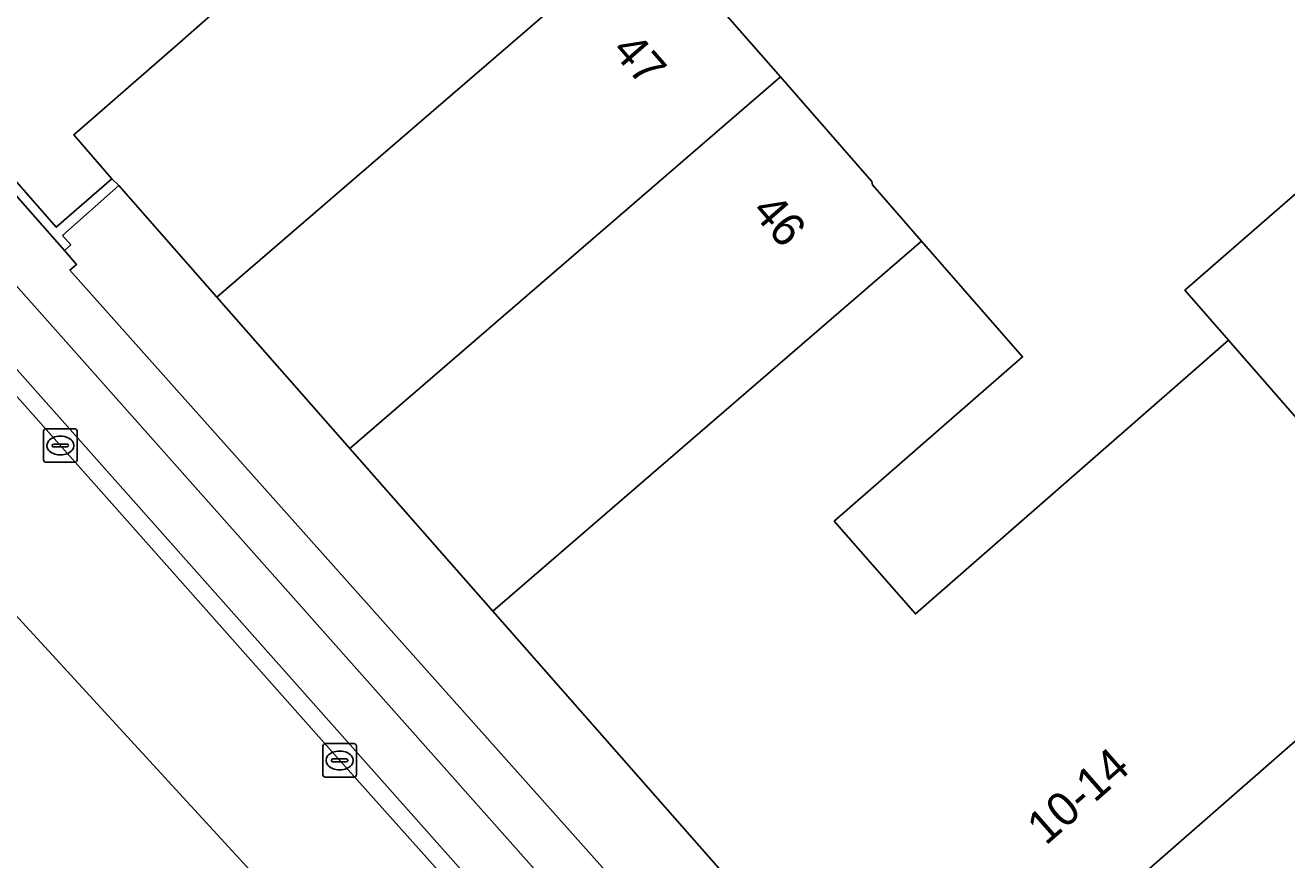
# Model space of a CAD drawing. Extents: x 160663 to 161506, y 382245 to 383291.
# Drawn here: x 160746.63 to 160784.22, y 383038.76 to 383063.64 of the extents above; entities that cross this region are included whole.
import ezdxf

# ---------------------------------------------------------------- set-up
doc = ezdxf.new("R2010")
doc.units = 0
for name, color, linetype in [('IMGEO_Berm_gesloten', 7, 'Continuous'), ('IMGEO_Erf', 7, 'Continuous'), ('IMGEO_Fietspad_gesloten', 7, 'Continuous'), ('IMGEO_Groenvoorziening', 7, 'Continuous'), ('IMGEO_Haag', 7, 'Continuous'), ('IMGEO_Kolk', 7, 'Continuous'), ('IMGEO_Muur', 7, 'Continuous'), ('IMGEO_Pand', 7, 'Continuous'), ('IMGEO_Pand_nummerreeks', 7, 'Continuous'), ('IMGEO_Rijbaan_lokaal_gesloten', 7, 'Continuous'), ('IMGEO_Voetpad_open', 7, 'Continuous')]:
    doc.layers.add(name, color=color, linetype=linetype)

msp = doc.modelspace()

# ---------------------------------------------------------------- linework, layer by layer
at = {"layer": 'IMGEO_Berm_gesloten'}
msp.add_lwpolyline([(160691.872, 383117.281), (160690.98, 383116.666), (160694.714, 383111.885), (160698.642, 383106.855), (160700.685, 383104.38), (160701.821, 383103.003), (160707.188, 383096.777), (160756.002, 383041.721), (160767.962, 383028.335), (160768.358, 383028.694), (160762.53, 383035.176), (160707.345, 383097.37)], dxfattribs=at)
at = {"layer": 'IMGEO_Erf'}
msp.add_lwpolyline([(160741.394, 383064.67), (160747.56, 383057.614), (160749.218, 383059.06), (160748.08, 383060.364), (160751.236, 383063.118), (160755.975, 383067.307), (160760.845, 383071.574), (160765.185, 383066.611), (160769.134, 383062.095), (160771.856, 383058.982), (160771.879, 383058.88), (160773.339, 383057.204), (160776.347, 383053.751), (160770.736, 383048.852), (160773.152, 383046.089), (160781.278, 383053.198), (160782.484, 383054.246), (160781.181, 383055.738), (160785.226, 383059.27)], dxfattribs=at)
at = {"layer": 'IMGEO_Fietspad_gesloten'}
msp.add_lwpolyline([(160694.239, 383113.304), (160699.114, 383107.117), (160701.082, 383104.713), (160702.219, 383103.325), (160707.345, 383097.37), (160762.53, 383035.176), (160768.358, 383028.694), (160770.443, 383028.844), (160763.764, 383036.278), (160718.771, 383086.968)], dxfattribs=at)
at = {"layer": 'IMGEO_Groenvoorziening'}
msp.add_lwpolyline([(160747.748, 383057.366), (160747.992, 383057.089), (160747.804, 383056.924), (160748.161, 383056.502), (160747.966, 383056.336), (160771.029, 383030.453), (160772.306, 383031.61), (160772.432, 383031.763), (160772.216, 383032.016), (160772.635, 383032.43), (160760.563, 383046.173), (160756.307, 383051.019), (160752.347, 383055.527), (160749.42, 383058.859)], close=True, dxfattribs=at)
at = {"layer": 'IMGEO_Haag'}
msp.add_lwpolyline([(160747.748, 383057.366), (160747.992, 383057.089), (160747.804, 383056.924), (160748.161, 383056.502), (160747.966, 383056.336), (160771.029, 383030.453), (160772.306, 383031.61), (160772.432, 383031.763), (160772.216, 383032.016), (160772.635, 383032.43), (160760.563, 383046.173), (160756.307, 383051.019), (160752.347, 383055.527), (160749.42, 383058.859)], close=True, dxfattribs=at)
at = {"layer": 'IMGEO_Kolk'}
for p, q in [((160747.18, 383050.681), (160747.18, 383051.533)), ((160747.255, 383051.607), (160748.107, 383051.607)), ((160747.668, 383051.387), (160747.693, 383051.387)), ((160748.181, 383051.533), (160748.181, 383050.681)), ((160747.439, 383051.101), (160747.439, 383051.113)), ((160747.877, 383051.064), (160747.479, 383051.064)), ((160747.482, 383051.15), (160747.88, 383051.15)), ((160747.923, 383051.113), (160747.923, 383051.101)), ((160747.691, 383050.827), (160747.666, 383050.827)), ((160748.107, 383050.607), (160747.255, 383050.607)), ((160755.501, 383041.295), (160755.501, 383042.147)), ((160755.576, 383042.221), (160756.428, 383042.221)), ((160755.989, 383042.001), (160756.014, 383042.001)), ((160756.502, 383042.147), (160756.502, 383041.295)), ((160755.76, 383041.715), (160755.76, 383041.727)), ((160756.198, 383041.678), (160755.8, 383041.678)), ((160755.803, 383041.764), (160756.201, 383041.764)), ((160756.244, 383041.727), (160756.244, 383041.715)), ((160756.428, 383041.221), (160755.576, 383041.221)), ((160756.012, 383041.441), (160755.987, 383041.441))]:
    msp.add_line(p, q, dxfattribs=at)
for points in [[(160747.18, 383050.681), (160747.18, 383051.533)], [(160747.255, 383051.607), (160748.107, 383051.607)], [(160748.181, 383051.533), (160748.181, 383050.681)], [(160748.107, 383050.607), (160747.255, 383050.607)], [(160755.501, 383041.295), (160755.501, 383042.147)], [(160755.576, 383042.221), (160756.428, 383042.221)], [(160756.502, 383042.147), (160756.502, 383041.295)], [(160756.428, 383041.221), (160755.576, 383041.221)]]:
    msp.add_lwpolyline(points, dxfattribs=at)
for centre, radius, start, end in [((160747.257, 383051.531), 0.0765, 91.552, 178.448), ((160747.257, 383051.531), 0.0765, 91.552, 178.448), ((160748.105, 383051.531), 0.0765, 1.552, 88.448), ((160748.105, 383051.531), 0.0765, 1.552, 88.448), ((160747.479, 383051.11), 0.0403, 85.8775, 175.7526), ((160747.476, 383051.1), 0.0366, 178.938, 274.7102), ((160747.88, 383051.107), 0.043, 264.8664, 352.4533), ((160747.884, 383051.112), 0.0386, 1.7309, 96.639), ((160747.257, 383050.683), 0.0765, 181.552, 268.448), ((160747.257, 383050.683), 0.0765, 181.552, 268.448), ((160748.105, 383050.683), 0.0765, 271.552, 358.448), ((160748.105, 383050.683), 0.0765, 271.552, 358.448), ((160755.578, 383042.145), 0.0765, 91.552, 178.448), ((160755.578, 383042.145), 0.0765, 91.552, 178.448), ((160756.426, 383042.145), 0.0765, 1.552, 88.448), ((160756.426, 383042.145), 0.0765, 1.552, 88.448), ((160755.8, 383041.724), 0.0403, 85.8775, 175.7526), ((160755.797, 383041.714), 0.0366, 178.938, 274.7102), ((160756.201, 383041.721), 0.043, 264.8664, 352.4533), ((160756.205, 383041.726), 0.0386, 1.7309, 96.639), ((160755.578, 383041.297), 0.0765, 181.552, 268.448), ((160755.578, 383041.297), 0.0765, 181.552, 268.448), ((160756.426, 383041.297), 0.0765, 271.552, 358.448), ((160756.426, 383041.297), 0.0765, 271.552, 358.448)]:
    msp.add_arc(centre, radius, start, end, dxfattribs=at)
for centre, major_axis, ratio, start_param, end_param in [((160747.667, 383051.107), (-0.387, 0.002), 0.722429, 4.712389, 7.853982), ((160747.692, 383051.107), (-0.39, 0.002), 0.717154, 1.570796, 4.712389), ((160755.988, 383041.721), (-0.387, 0.002), 0.722429, 4.712389, 7.853982), ((160756.013, 383041.721), (-0.39, 0.002), 0.717154, 1.570796, 4.712389)]:
    msp.add_ellipse(centre, major_axis=major_axis, ratio=ratio, start_param=start_param, end_param=end_param, dxfattribs=at)
at = {"layer": 'IMGEO_Muur'}
msp.add_lwpolyline([(160747.804, 383056.924), (160747.992, 383057.089), (160747.748, 383057.366), (160749.42, 383058.859), (160749.218, 383059.06), (160747.56, 383057.614), (160741.394, 383064.67), (160743.052, 383066.116), (160742.859, 383066.32), (160741.176, 383064.836), (160740.918, 383065.129), (160740.73, 383064.964)], close=True, dxfattribs=at)
at = {"layer": 'IMGEO_Pand'}
for points in [[(160765.185, 383066.611), (160760.845, 383071.574), (160755.975, 383067.307), (160751.236, 383063.118), (160748.08, 383060.364), (160749.218, 383059.06), (160749.42, 383058.859), (160752.347, 383055.527)], [(160756.307, 383051.019), (160769.134, 383062.095), (160765.185, 383066.611), (160752.347, 383055.527)], [(160760.563, 383046.173), (160773.339, 383057.204), (160771.879, 383058.88), (160771.856, 383058.982), (160769.134, 383062.095), (160756.307, 383051.019)], [(160788.458, 383047.394), (160792.5, 383050.926), (160785.226, 383059.27), (160781.181, 383055.738), (160782.484, 383054.246)], [(160760.563, 383046.173), (160772.635, 383032.43), (160772.216, 383032.016), (160772.432, 383031.763), (160772.871, 383032.154), (160773.088, 383031.903), (160773.344, 383032.118), (160773.126, 383032.378), (160773.657, 383032.835), (160785.093, 383042.838), (160785.404, 383042.466), (160788.374, 383045.042), (160787.902, 383045.586), (160788.84, 383046.396), (160788.94, 383046.482), (160788.287, 383047.244), (160788.458, 383047.394), (160782.484, 383054.246), (160781.278, 383053.198), (160773.152, 383046.089), (160770.736, 383048.852), (160776.347, 383053.751), (160773.339, 383057.204)]]:
    msp.add_lwpolyline(points, close=True, dxfattribs=at)
at = {"layer": 'IMGEO_Rijbaan_lokaal_gesloten'}
for points in [[(160845.035, 382944.34), (160842.06, 382947.363), (160830.64, 382959.7), (160777.232, 383018.081), (160767.962, 383028.335), (160756.002, 383041.721), (160707.188, 383096.777), (160701.821, 383103.003), (160700.685, 383104.38), (160698.642, 383106.855), (160694.714, 383111.885), (160692.256, 383109.63)], [(160691.463, 383108.887), (160690.092, 383107.358), (160792.96, 382995.267), (160844.823, 382938.754), (160856.414, 382930.084)]]:
    msp.add_lwpolyline(points, dxfattribs=at)
at = {"layer": 'IMGEO_Voetpad_open'}
for points in [[(160696.071, 383113.574), (160702.367, 383105.793), (160703.534, 383104.351), (160718.771, 383086.968), (160763.764, 383036.278), (160770.443, 383028.844), (160772.34, 383028.989), (160771.029, 383030.453), (160747.966, 383056.336), (160748.161, 383056.502), (160747.804, 383056.924), (160740.73, 383064.964), (160740.378, 383065.36), (160740.251, 383065.247), (160729.683, 383077.158)], [(160848.555, 383094.624), (160847.06, 383096.364), (160809.442, 383063.5), (160809.549, 383063.39), (160807.695, 383061.773), (160807.556, 383061.652), (160804.354, 383058.755), (160789.437, 383045.729), (160788.84, 383046.396), (160787.902, 383045.586), (160788.374, 383045.042), (160785.404, 383042.466), (160785.093, 383042.838), (160773.657, 383032.835), (160773.126, 383032.378), (160773.344, 383032.118), (160773.088, 383031.903), (160772.871, 383032.154), (160772.432, 383031.763), (160772.306, 383031.61), (160771.029, 383030.453), (160772.34, 383028.989)]]:
    msp.add_lwpolyline(points, dxfattribs=at)

# ---------------------------------------------------------------- texts
at = {"layer": 'IMGEO_Pand_nummerreeks'}
for s, rotation, p in [('47', 311.0053, (160764.075, 383062.861)), ('46', 311.0053, (160768.24, 383058.071)), ('10-14', 41.2871, (160777.035, 383039.164))]:
    msp.add_text(s, height=1, rotation=rotation, dxfattribs=at).set_placement(p)

doc.saveas('drawing.dxf')
